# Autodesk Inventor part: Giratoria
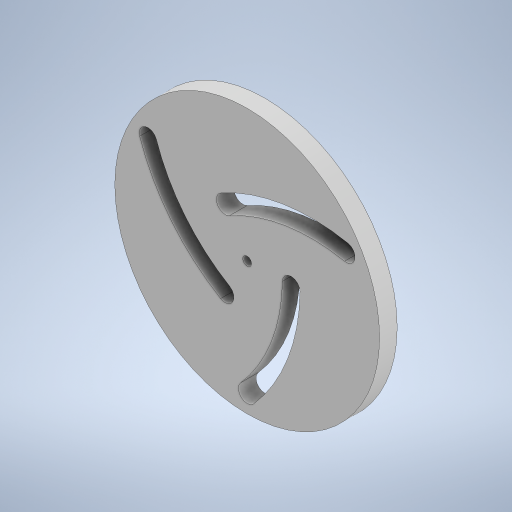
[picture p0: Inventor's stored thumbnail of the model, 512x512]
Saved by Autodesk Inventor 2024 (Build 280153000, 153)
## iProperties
Created: 2024-05
Part Number: Giratoria
Material: Generic
Document SubType Name: Modeling
Designer: dylan
Density: 1 g/cm^3
Appearance: Default
Author: dylan
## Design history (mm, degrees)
sketch "Sketch1"
  geometry: L1 (0, 0)-(0, -60); C1 r 75.15 at (-16.974, -101.222) reference; A1 r 5 centre (8.026, -101.222) between (8.026, -96.222) and (8.026, -106.222) reference; A2 r 5 centre (-16.974, -166.222) between (-21.974, -166.222) and (-11.974, -166.222) reference; A3 r 5 centre (8.026, -101.222) between (13.026, -101.288) and (3.027, -101.156); A4 r 5 centre (-16.974, -166.222) between (-20.729, -162.921) and (-13.218, -169.523); A5 r 100.45 centre (-92.415, -99.899) between (-16.974, -166.222) and (8.026, -101.222); A6 r 105.45 centre (-92.415, -99.899) between (-13.218, -169.523) and (13.026, -101.288); A7 r 95.45 centre (-92.415, -99.899) between (-20.729, -162.921) and (3.027, -101.156); A8 r 5 centre (-16.974, -166.222) between (-20.729, -162.921) and (-13.218, -169.523); A9 r 5 centre (8.026, -101.222) between (13.026, -101.288) and (3.027, -101.156); A10 r 5 centre (-29.474, -79.571) between (-31.916, -75.209) and (-27.031, -83.934); A11 r 105.45 centre (19.601, -167.218) between (40.299, -63.819) and (-31.916, -75.209); A12 r 5 centre (-29.474, -79.571) between (-31.916, -75.209) and (-27.031, -83.934); A13 r 95.45 centre (19.601, -167.218) between (38.337, -73.625) and (-27.031, -83.934); A14 r 5 centre (39.318, -68.722) between (38.337, -73.625) and (40.299, -63.819); A15 r 5 centre (-29.474, -122.873) between (-32.03, -127.169) and (-26.917, -118.576); A16 r 105.45 centre (21.893, -36.55) between (-78.002, -70.323) and (-32.03, -127.169); A17 r 5 centre (-29.474, -122.873) between (-32.03, -127.169) and (-26.917, -118.576); A18 r 95.45 centre (21.893, -36.55) between (-68.529, -67.121) and (-26.917, -118.576); A19 r 5 centre (-73.265, -68.722) between (-68.529, -67.121) and (-78.002, -70.323); 4 further points
  constraints: 34 point on circle, 17 centre point, 4 tangent, 2 coincident, 2 end point, 1 concentric, 1 vertical, 37 other
  dimensions: "d11" = 360 deg dimension on C1.centre A3.centre (derived)
extrude "Extrusion1" new body sketch "Sketch1" distance "d4" = 10; taper "d5" = 0 deg
sketch "Sketch2"
  geometry: C1 r 2.5 at (0, 0); 1 further point
  constraints: 1 centre point
  dimensions: "d6" = 5 diameter of C1
extrude "Extrusion2" cut sketch "Sketch2" distance "d7" = 10; taper "d8" = 0 deg
body "Solid1"
node "Reference1"
node "Reference2"
node "Reference3"
